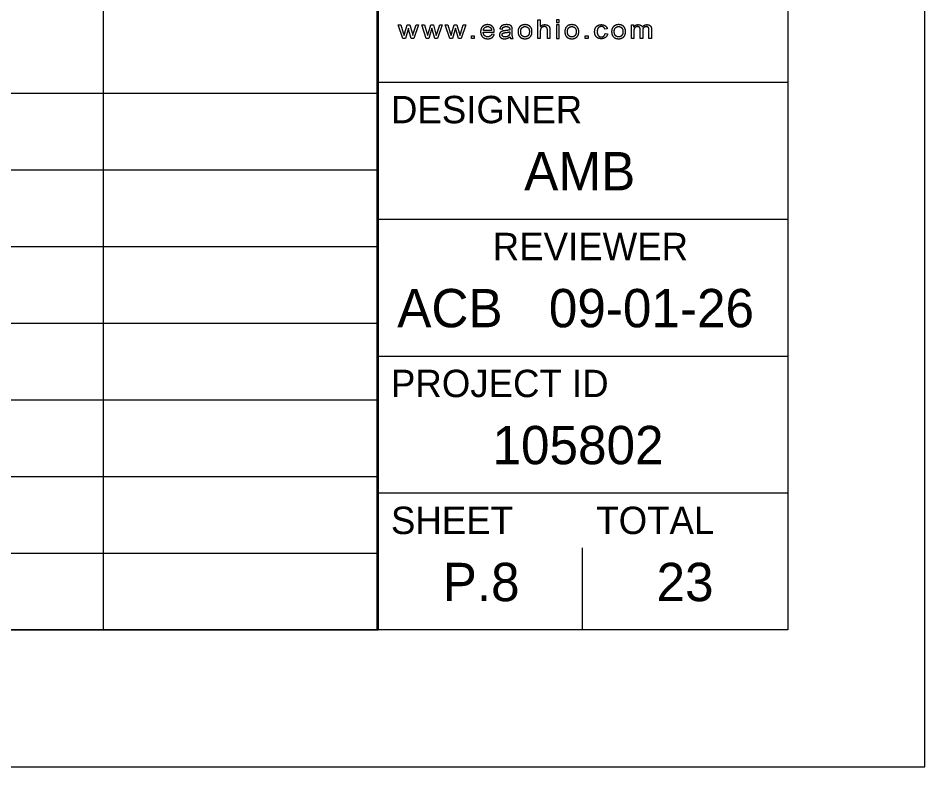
# Model space of a CAD drawing. Extents: x 0 to 34, y 0 to 22.
# Drawn here: x 30.688 to 34, y 0 to 2.734 of the extents above; entities that cross this region are included whole.
import ezdxf

# ---------------------------------------------------------------- set-up
doc = ezdxf.new("R2010")
doc.units = 0
for name, color, linetype in [('SH_Border', 7, 'Continuous'), ('SH_Cut_Line', 7, 'Continuous'), ('SH_Data', 7, 'Continuous'), ('TX_X_20', 7, 'Continuous')]:
    doc.layers.add(name, color=color, linetype=linetype)

msp = doc.modelspace()

# ---------------------------------------------------------------- linework, layer by layer
at = {"layer": 'SH_Border'}
for p, q in [((32, 0.5), (32, 21.5)), ((32, 2.5), (33.5, 2.5)), ((32, 2), (33.5, 2)), ((32, 1.5), (33.5, 1.5)), ((32, 1), (33.5, 1))]:
    msp.add_line(p, q, dxfattribs=at)
msp.add_lwpolyline([(1.5, 21.5), (33.5, 21.5), (33.5, 0.5), (1.5, 0.5)], close=True, dxfattribs=at)
at = {"layer": 'SH_Cut_Line'}
msp.add_lwpolyline([(0, 0), (34, 0), (34, 22), (0, 22)], close=True, dxfattribs=at)
at = {"layer": 'SH_Data'}
for p, q in [((30.9988, 21.5), (30.9988, 0.5)), ((32.0036, 21.5), (32.0036, 0.5)), ((1.5, 2.46), (32.0036, 2.46)), ((1.5, 2.18), (32.0036, 2.18)), ((1.5, 1.9), (32.0036, 1.9)), ((1.5, 1.62), (32.0036, 1.62)), ((1.5, 1.34), (32.0036, 1.34)), ((1.5, 1.06), (32.0036, 1.06)), ((32.75, 0.5), (32.75, 0.8)), ((1.5, 0.78), (32.0036, 0.78)), ((32.375, 0.675), (32.375, 0.675)), ((1.5, 0.5), (32.0036, 0.5))]:
    msp.add_line(p, q, dxfattribs=at)
at = {"layer": 'TX_X_20'}
for p, q in [((32.4178, 2.6889), (32.3875, 2.6889)), ((32.4477, 2.6948), (32.4567, 2.6937)), ((32.4838, 2.6843), (32.4838, 2.6812)), ((32.4931, 2.6802), (32.4931, 2.6913)), ((32.5143, 2.6842), (32.5143, 2.6842)), ((32.5238, 2.6842), (32.5238, 2.6842)), ((32.6852, 2.6842), (32.6852, 2.6842)), ((32.6946, 2.6842), (32.6946, 2.6842)), ((32.8402, 2.6944), (32.8313, 2.6931)), ((32.856, 2.6842), (32.856, 2.6842)), ((32.8655, 2.6842), (32.8655, 2.6842)), ((32.387, 2.6821), (32.4274, 2.6821)), ((32.4272, 2.6744), (32.4177, 2.6755)), ((32.4846, 2.6656), (32.4846, 2.6656)), ((32.4864, 2.6596), (32.496, 2.6596)), ((32.8321, 2.6776), (32.8411, 2.6765))]:
    msp.add_line(p, q, dxfattribs=at)
for points in [[(32.5955, 2.6865), (32.5955, 2.6596), (32.5863, 2.6596), (32.5863, 2.7276), (32.5955, 2.7276), (32.5955, 2.7032)], [(32.1007, 2.68), (32.1093, 2.7089), (32.1188, 2.7089), (32.1269, 2.6802), (32.1295, 2.6708), (32.1327, 2.6804), (32.142, 2.7089), (32.1509, 2.7089), (32.1339, 2.6596), (32.1244, 2.6596), (32.1158, 2.6891), (32.1137, 2.6975), (32.1027, 2.6596), (32.0931, 2.6596), (32.0766, 2.7089), (32.0861, 2.7089), (32.0947, 2.6804), (32.0979, 2.6698)], [(32.1867, 2.68), (32.1953, 2.7089), (32.2048, 2.7089), (32.2129, 2.6802), (32.2155, 2.6708), (32.2186, 2.6804), (32.228, 2.7089), (32.2369, 2.7089), (32.2199, 2.6596), (32.2104, 2.6596), (32.2018, 2.6891), (32.1997, 2.6975), (32.1886, 2.6596), (32.179, 2.6596), (32.1625, 2.7089), (32.172, 2.7089), (32.1807, 2.6804), (32.1838, 2.6698)], [(32.2726, 2.68), (32.2813, 2.7089), (32.2907, 2.7089), (32.2988, 2.6802), (32.3015, 2.6708), (32.3046, 2.6804), (32.3139, 2.7089), (32.3229, 2.7089), (32.3059, 2.6596), (32.2964, 2.6596), (32.2878, 2.6891), (32.2856, 2.6975), (32.2746, 2.6596), (32.265, 2.6596), (32.2485, 2.7089), (32.258, 2.7089), (32.2666, 2.6804), (32.2698, 2.6698)], [(32.6305, 2.6908), (32.6305, 2.6596), (32.6213, 2.6596), (32.6213, 2.6908)], [(32.9372, 2.6851), (32.9372, 2.6596), (32.928, 2.6596), (32.928, 2.7089), (32.9362, 2.7089), (32.9362, 2.7019)], [(32.9694, 2.6882), (32.9694, 2.6596), (32.9602, 2.6596), (32.9602, 2.6916)], [(33.0015, 2.6934), (33.0015, 2.6596), (32.9923, 2.6596), (32.9923, 2.6906)]]:
    msp.add_lwpolyline(points, dxfattribs=at)
for points in [[(32.655, 2.718), (32.6642, 2.718), (32.6642, 2.7276), (32.655, 2.7276)], [(32.655, 2.6596), (32.6642, 2.6596), (32.6642, 2.7089), (32.655, 2.7089)], [(32.3437, 2.6596), (32.3437, 2.669), (32.3541, 2.669), (32.3541, 2.6596)], [(32.7597, 2.6596), (32.7597, 2.669), (32.7702, 2.669), (32.7702, 2.6596)]]:
    msp.add_lwpolyline(points, close=True, dxfattribs=at)
for points in [[(32.3846, 2.7031), (32.3775, 2.6962), (32.3775, 2.6838)], [(32.3775, 2.6838), (32.3775, 2.6718), (32.3845, 2.6651)], [(32.4028, 2.71), (32.3916, 2.71), (32.3846, 2.7031)], [(32.3875, 2.6889), (32.388, 2.6954), (32.3923, 2.6992)], [(32.3923, 2.6992), (32.3966, 2.7031), (32.4029, 2.7031)], [(32.4206, 2.7032), (32.4137, 2.71), (32.4028, 2.71)], [(32.4029, 2.7031), (32.4099, 2.7031), (32.4143, 2.6983)], [(32.4143, 2.6983), (32.4172, 2.6951), (32.4178, 2.6889)], [(32.4275, 2.6843), (32.4275, 2.6965), (32.4206, 2.7032)], [(32.4274, 2.6821), (32.4275, 2.6835), (32.4275, 2.6843)], [(32.4517, 2.7032), (32.4489, 2.7), (32.4477, 2.6948)], [(32.4526, 2.684), (32.4497, 2.6822), (32.4479, 2.6792)], [(32.4598, 2.7082), (32.4545, 2.7065), (32.4517, 2.7032)], [(32.4592, 2.6867), (32.4555, 2.6858), (32.4526, 2.684)], [(32.4567, 2.6937), (32.4581, 2.6989), (32.4612, 2.701)], [(32.4674, 2.688), (32.4619, 2.6873), (32.4592, 2.6867)], [(32.4721, 2.71), (32.4651, 2.71), (32.4598, 2.7082)], [(32.4612, 2.701), (32.4643, 2.7031), (32.4708, 2.7031)], [(32.4838, 2.6908), (32.4785, 2.6892), (32.4674, 2.688)], [(32.4688, 2.6811), (32.4788, 2.6824), (32.4838, 2.6843)], [(32.4708, 2.7031), (32.4777, 2.7031), (32.4812, 2.7002)], [(32.4834, 2.7085), (32.479, 2.71), (32.4721, 2.71)], [(32.4812, 2.7002), (32.4838, 2.6981), (32.4838, 2.693)], [(32.4897, 2.7047), (32.4877, 2.707), (32.4834, 2.7085)], [(32.4838, 2.693), (32.4838, 2.6925), (32.4838, 2.6908)], [(32.4926, 2.699), (32.4918, 2.7025), (32.4897, 2.7047)], [(32.4931, 2.6913), (32.4931, 2.6969), (32.4926, 2.699)], [(32.5227, 2.7045), (32.5143, 2.6979), (32.5143, 2.6842)], [(32.5143, 2.6842), (32.5143, 2.6717), (32.5214, 2.6651)], [(32.5398, 2.71), (32.5297, 2.71), (32.5227, 2.7045)], [(32.5238, 2.6842), (32.5238, 2.6937), (32.5283, 2.6984)], [(32.5283, 2.67), (32.5238, 2.6747), (32.5238, 2.6842)], [(32.5283, 2.6984), (32.5329, 2.7031), (32.5398, 2.7031)], [(32.558, 2.7033), (32.5509, 2.71), (32.5398, 2.71)], [(32.5398, 2.7031), (32.5465, 2.7031), (32.5511, 2.6983)], [(32.5511, 2.6983), (32.5556, 2.6936), (32.5556, 2.6845)], [(32.5556, 2.6845), (32.5556, 2.6748), (32.5511, 2.6701)], [(32.5651, 2.6849), (32.5651, 2.6966), (32.558, 2.7033)], [(32.562, 2.67), (32.5651, 2.6754), (32.5651, 2.6849)], [(32.5955, 2.7032), (32.602, 2.71), (32.6118, 2.71)], [(32.5971, 2.6956), (32.5955, 2.6923), (32.5955, 2.6865)], [(32.6022, 2.7008), (32.5986, 2.6989), (32.5971, 2.6956)], [(32.6099, 2.7028), (32.6058, 2.7028), (32.6022, 2.7008)], [(32.6183, 2.6999), (32.6153, 2.7028), (32.6099, 2.7028)], [(32.6118, 2.71), (32.6178, 2.71), (32.6222, 2.7078)], [(32.6213, 2.6908), (32.6213, 2.697), (32.6183, 2.6999)], [(32.6222, 2.7078), (32.6267, 2.7056), (32.6286, 2.7018)], [(32.6286, 2.7018), (32.6305, 2.698), (32.6305, 2.6908)], [(32.6935, 2.7045), (32.6852, 2.6979), (32.6852, 2.6842)], [(32.6852, 2.6842), (32.6852, 2.6717), (32.6922, 2.6651)], [(32.7106, 2.71), (32.7005, 2.71), (32.6935, 2.7045)], [(32.6946, 2.6842), (32.6946, 2.6937), (32.6992, 2.6984)], [(32.6992, 2.67), (32.6946, 2.6747), (32.6946, 2.6842)], [(32.6992, 2.6984), (32.7037, 2.7031), (32.7106, 2.7031)], [(32.7288, 2.7033), (32.7218, 2.71), (32.7106, 2.71)], [(32.7106, 2.7031), (32.7174, 2.7031), (32.7219, 2.6983)], [(32.7219, 2.6983), (32.7265, 2.6936), (32.7265, 2.6845)], [(32.7265, 2.6845), (32.7265, 2.6748), (32.7219, 2.6701)], [(32.7359, 2.6849), (32.7359, 2.6966), (32.7288, 2.7033)], [(32.7328, 2.67), (32.7359, 2.6754), (32.7359, 2.6849)], [(32.7939, 2.684), (32.7939, 2.692), (32.7968, 2.698)], [(32.8006, 2.6651), (32.7939, 2.6717), (32.7939, 2.684)], [(32.7968, 2.698), (32.7997, 2.704), (32.8056, 2.707)], [(32.8077, 2.6986), (32.8033, 2.6941), (32.8033, 2.6843)], [(32.8033, 2.6843), (32.8033, 2.6743), (32.8075, 2.6698)], [(32.8056, 2.707), (32.8116, 2.71), (32.8186, 2.71)], [(32.8189, 2.7031), (32.812, 2.7031), (32.8077, 2.6986)], [(32.8186, 2.71), (32.8274, 2.71), (32.833, 2.7059)], [(32.8268, 2.7006), (32.8235, 2.7031), (32.8189, 2.7031)], [(32.8313, 2.6931), (32.83, 2.6981), (32.8268, 2.7006)], [(32.833, 2.7059), (32.8387, 2.7018), (32.8402, 2.6944)], [(32.8644, 2.7045), (32.856, 2.6979), (32.856, 2.6842)], [(32.856, 2.6842), (32.856, 2.6717), (32.863, 2.6651)], [(32.8814, 2.71), (32.8714, 2.71), (32.8644, 2.7045)], [(32.8655, 2.6842), (32.8655, 2.6937), (32.87, 2.6984)], [(32.87, 2.67), (32.8655, 2.6747), (32.8655, 2.6842)], [(32.87, 2.6984), (32.8745, 2.7031), (32.8814, 2.7031)], [(32.8997, 2.7033), (32.8926, 2.71), (32.8814, 2.71)], [(32.8814, 2.7031), (32.8882, 2.7031), (32.8927, 2.6983)], [(32.8927, 2.6983), (32.8973, 2.6936), (32.8973, 2.6845)], [(32.8973, 2.6845), (32.8973, 2.6748), (32.8928, 2.6701)], [(32.9068, 2.6849), (32.9068, 2.6966), (32.8997, 2.7033)], [(32.9036, 2.67), (32.9068, 2.6754), (32.9068, 2.6849)], [(32.9362, 2.7019), (32.9388, 2.7055), (32.943, 2.7077)], [(32.9387, 2.6954), (32.9372, 2.6918), (32.9372, 2.6851)], [(32.9434, 2.7008), (32.9401, 2.699), (32.9387, 2.6954)], [(32.943, 2.7077), (32.9472, 2.71), (32.9527, 2.71)], [(32.9506, 2.7027), (32.9467, 2.7027), (32.9434, 2.7008)], [(32.958, 2.6999), (32.9557, 2.7027), (32.9506, 2.7027)], [(32.9527, 2.71), (32.9587, 2.71), (32.9625, 2.7077)], [(32.9602, 2.6916), (32.9602, 2.6971), (32.958, 2.6999)], [(32.9625, 2.7077), (32.9664, 2.7054), (32.968, 2.7013)], [(32.968, 2.7013), (32.9744, 2.71), (32.9847, 2.71)], [(32.9732, 2.6992), (32.9694, 2.6958), (32.9694, 2.6882)], [(32.9827, 2.7027), (32.977, 2.7027), (32.9732, 2.6992)], [(32.9882, 2.7014), (32.9858, 2.7027), (32.9827, 2.7027)], [(32.9847, 2.71), (32.9928, 2.71), (32.9972, 2.7059)], [(32.9914, 2.6978), (32.9905, 2.7), (32.9882, 2.7014)], [(32.9923, 2.6906), (32.9923, 2.6956), (32.9914, 2.6978)], [(32.9972, 2.7059), (33.0015, 2.7018), (33.0015, 2.6934)], [(32.0979, 2.6698), (32.0981, 2.6706), (32.1007, 2.68)], [(32.1838, 2.6698), (32.184, 2.6706), (32.1867, 2.68)], [(32.2698, 2.6698), (32.27, 2.6706), (32.2726, 2.68)], [(32.3845, 2.6651), (32.3915, 2.6585), (32.4034, 2.6585)], [(32.3921, 2.6696), (32.3875, 2.6739), (32.387, 2.6821)], [(32.4034, 2.6653), (32.3966, 2.6653), (32.3921, 2.6696)], [(32.412, 2.6677), (32.4085, 2.6653), (32.4034, 2.6653)], [(32.4034, 2.6585), (32.4128, 2.6585), (32.4189, 2.6626)], [(32.4177, 2.6755), (32.4156, 2.6702), (32.412, 2.6677)], [(32.4189, 2.6626), (32.4249, 2.6668), (32.4272, 2.6744)], [(32.4479, 2.6792), (32.4461, 2.6762), (32.4461, 2.6726)], [(32.4461, 2.6726), (32.4461, 2.6664), (32.4509, 2.6624)], [(32.4509, 2.6624), (32.4556, 2.6585), (32.4646, 2.6585)], [(32.4559, 2.6728), (32.4559, 2.675), (32.4571, 2.6768)], [(32.4586, 2.6672), (32.4559, 2.6695), (32.4559, 2.6728)], [(32.4571, 2.6768), (32.4584, 2.6785), (32.4608, 2.6795)], [(32.4668, 2.665), (32.4614, 2.665), (32.4586, 2.6672)], [(32.4608, 2.6795), (32.4631, 2.6804), (32.4688, 2.6811)], [(32.4646, 2.6585), (32.47, 2.6585), (32.4747, 2.6601)], [(32.4762, 2.6671), (32.4721, 2.665), (32.4668, 2.665)], [(32.4747, 2.6601), (32.4794, 2.6617), (32.4846, 2.6656)], [(32.4823, 2.6729), (32.4803, 2.6692), (32.4762, 2.6671)], [(32.4838, 2.6812), (32.4838, 2.6757), (32.4823, 2.6729)], [(32.4846, 2.6656), (32.485, 2.6622), (32.4864, 2.6596)], [(32.4936, 2.6655), (32.4931, 2.6686), (32.4931, 2.6802)], [(32.496, 2.6596), (32.4942, 2.6624), (32.4936, 2.6655)], [(32.5214, 2.6651), (32.5284, 2.6585), (32.5398, 2.6585)], [(32.5398, 2.6653), (32.5329, 2.6653), (32.5283, 2.67)], [(32.5511, 2.6701), (32.5466, 2.6653), (32.5398, 2.6653)], [(32.5398, 2.6585), (32.5468, 2.6585), (32.5528, 2.6615)], [(32.5528, 2.6615), (32.5588, 2.6645), (32.562, 2.67)], [(32.6922, 2.6651), (32.6992, 2.6585), (32.7106, 2.6585)], [(32.7106, 2.6653), (32.7037, 2.6653), (32.6992, 2.67)], [(32.7219, 2.6701), (32.7174, 2.6653), (32.7106, 2.6653)], [(32.7106, 2.6585), (32.7177, 2.6585), (32.7237, 2.6615)], [(32.7237, 2.6615), (32.7297, 2.6645), (32.7328, 2.67)], [(32.8185, 2.6585), (32.8074, 2.6585), (32.8006, 2.6651)], [(32.8075, 2.6698), (32.8117, 2.6653), (32.8185, 2.6653)], [(32.8185, 2.6653), (32.8239, 2.6653), (32.8275, 2.6683)], [(32.8335, 2.6633), (32.8274, 2.6585), (32.8185, 2.6585)], [(32.8275, 2.6683), (32.8311, 2.6713), (32.8321, 2.6776)], [(32.8411, 2.6765), (32.8396, 2.668), (32.8335, 2.6633)], [(32.863, 2.6651), (32.87, 2.6585), (32.8814, 2.6585)], [(32.8814, 2.6653), (32.8745, 2.6653), (32.87, 2.67)], [(32.8928, 2.6701), (32.8882, 2.6653), (32.8814, 2.6653)], [(32.8814, 2.6585), (32.8885, 2.6585), (32.8945, 2.6615)], [(32.8945, 2.6615), (32.9005, 2.6645), (32.9036, 2.67)]]:
    msp.add_open_spline(points, degree=2, dxfattribs=at)

# ---------------------------------------------------------------- texts
at = {"layer": 'SH_Data'}
for s, height, p in [('DESIGNER', 0.1, (32.05, 2.35)), ('AMB', 0.14, (32.5366, 2.105)), ('REVIEWER', 0.1, (32.4218, 1.85)), ('ACB', 0.14, (32.0729, 1.605)), ('09-01-26', 0.14, (32.6266, 1.605)), ('PROJECT ID', 0.1, (32.05, 1.35)), ('105802', 0.14, (32.4209, 1.105)), ('SHEET', 0.1, (32.05, 0.85)), ('TOTAL', 0.1, (32.8, 0.85)), ('P.8', 0.14, (32.2388, 0.605)), ('23', 0.14, (33.02, 0.605))]:
    msp.add_text(s, height=height, dxfattribs=at).set_placement(p)

doc.saveas('drawing.dxf')
